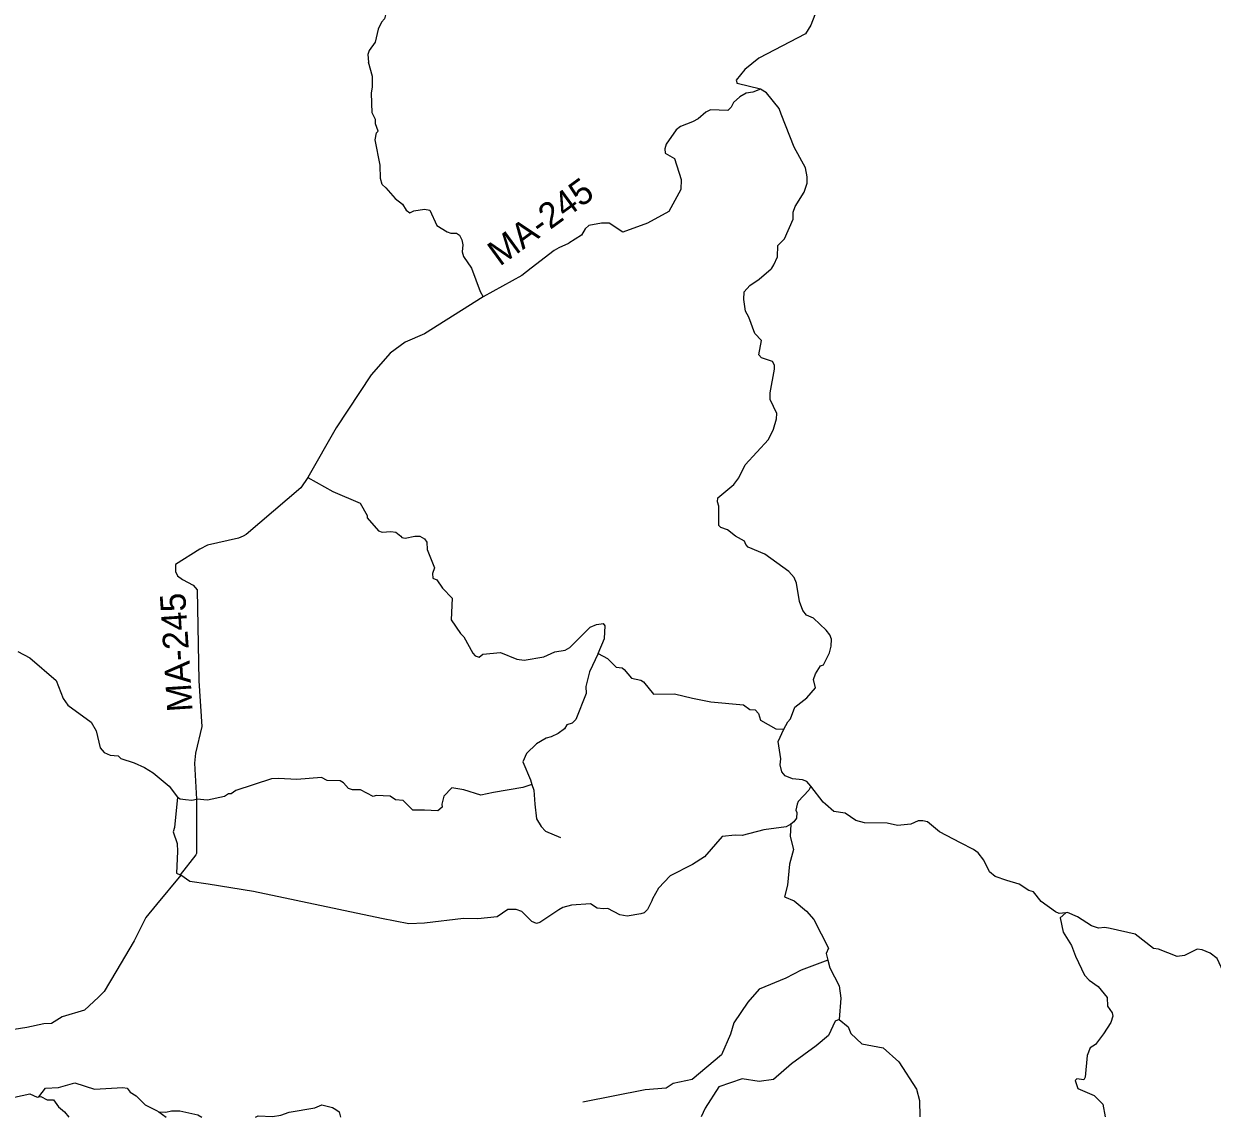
# Model space of a CAD drawing. Extents: x 332 to 501, y 9447 to 9559.
# Drawn here: x 458.02 to 475.76, y 9447.32 to 9463.65 of the extents above; entities that cross this region are included whole.
import ezdxf

# ---------------------------------------------------------------- set-up
doc = ezdxf.new("R2010")
doc.units = 0
for name, color, linetype in [('Level 31', 7, 'Continuous'), ('Level 4', 7, 'Continuous'), ('Level 5', 7, 'Continuous'), ('Level 6', 7, 'Continuous')]:
    doc.layers.add(name, color=color, linetype=linetype)

msp = doc.modelspace()

# ---------------------------------------------------------------- linework, layer by layer
at = {"layer": 'Level 4'}
for points in [[(469.9088, 9464), (469.7674, 9463.6267), (469.6871, 9463.4998), (468.9867, 9463.1333), (468.7796, 9462.9683), (468.6527, 9462.8055), (468.6652, 9462.7597)], [(469.0145, 9462.6735), (468.8979, 9462.6263), (468.7979, 9462.6109), (468.7055, 9462.557), (468.6132, 9462.4724), (468.5748, 9462.404), (468.5251, 9462.3543), (468.269, 9462.362), (468.1964, 9462.3314), (468.0817, 9462.232), (467.9999, 9462.1836)], [(469.0145, 9462.6735), (468.6652, 9462.7597)], [(469.102, 9462.62), (469.0145, 9462.6735)], [(467.9999, 9462.1836), (467.8217, 9462.1173), (467.7567, 9462.0676), (467.6038, 9461.8497), (467.5847, 9461.7809), (467.5923, 9461.7197), (467.73, 9461.6356), (467.8294, 9461.3221), (467.8255, 9461.173), (467.6459, 9460.8442), (467.3267, 9460.6702), (466.9597, 9460.5402), (466.7571, 9460.6702), (466.6386, 9460.674), (466.4513, 9460.6358), (466.3977, 9460.5861), (466.3404, 9460.4943), (466.1531, 9460.3719)], [(466.1504, 9460.3707), (466.003, 9460.3035)], [(466.1531, 9460.3719), (466.1504, 9460.3707)], [(466.003, 9460.3035), (465.9325, 9460.2648), (465.5921, 9460)], [(465.5921, 9460), (465.4508, 9459.8901), (464.876, 9459.574)], [(464.876, 9459.574), (463.9999, 9459.0191)], [(463.9999, 9459.0191), (463.7099, 9458.8942), (463.4881, 9458.7336), (463.2021, 9458.4085), (462.6784, 9457.6153), (462.2574, 9456.8764)], [(462.2574, 9456.8764), (462.1536, 9456.7192), (461.3393, 9456.023), (461.29, 9456)], [(461.29, 9456), (461.2246, 9455.9695), (460.7621, 9455.8624), (460.6435, 9455.805), (460.2804, 9455.5755), (460.2804, 9455.4722), (460.3109, 9455.4072), (460.3874, 9455.3498), (460.548, 9455.2695), (460.6053, 9455.1968), (460.6321, 9453.8418), (460.6779, 9453.1553), (460.5824, 9452.7613), (460.5671, 9452.6083), (460.5935, 9452.0726)], [(460.5935, 9452.0726), (460.5964, 9452)], [(460.5964, 9452), (460.5977, 9451.2609), (460.5838, 9451.2392)], [(460.5838, 9451.2392), (460.3544, 9450.9413)], [(460.3625, 9450.938), (460, 9450.5006)], [(460, 9450.5006), (459.8391, 9450.3064), (459.6658, 9449.9597), (459.392, 9449.493)], [(459.392, 9449.493), (459.22, 9449.1998), (459.1356, 9449.118)], [(459.1356, 9449.118), (458.9228, 9448.921), (458.5884, 9448.8219), (458.4336, 9448.7228), (458.316, 9448.7166), (458.0652, 9448.6651)], [(458.0652, 9448.6651), (457.8764, 9448.636), (457.519, 9448.4954)]]:
    msp.add_lwpolyline(points, dxfattribs=at)
at = {"layer": 'Level 5'}
for points in [[(463.4729, 9464), (463.4013, 9463.7216), (463.3572, 9463.6719), (463.3076, 9463.5695), (463.2635, 9463.3765), (463.1754, 9463.2497), (463.1534, 9463.1891), (463.1644, 9463.0763)], [(463.3076, 9462.0466), (463.2691, 9462.1557), (463.2691, 9462.2218), (463.2195, 9462.321), (463.2085, 9462.6132), (463.225, 9462.707), (463.225, 9462.8613), (463.1644, 9463.0763)], [(469.3222, 9462.2982), (469.29, 9462.382), (469.102, 9462.62)], [(469.5032, 9460.8384), (469.533, 9460.919), (469.665, 9461.133), (469.708, 9461.268), (469.709, 9461.366), (469.684, 9461.5), (469.515, 9461.807), (469.3222, 9462.2982)], [(469.274, 9460.337), (469.373, 9460.436), (469.502, 9460.733)], [(469.502, 9460.733), (469.5032, 9460.8384)], [(469.215, 9460.048), (469.267, 9460.1681), (469.274, 9460.337)], [(468.992, 9459.835), (469.174, 9459.989)], [(469.174, 9459.989), (469.1816, 9460)], [(469.1816, 9460), (469.215, 9460.048)], [(468.7668, 9459.5301), (468.768, 9459.646), (468.855, 9459.743), (468.992, 9459.835)], [(469.1574, 9458.1415), (469.223, 9458.4911), (469.221, 9458.55), (469.1941, 9458.607), (469.028, 9458.662), (468.991, 9458.706), (469.029, 9458.92), (468.927, 9459.024), (468.8379, 9459.27), (468.79, 9459.356), (468.7668, 9459.5301)], [(468.6151, 9456.7693), (468.6879, 9456.869), (468.786, 9457.064), (469.135, 9457.442), (469.209, 9457.598), (469.255, 9457.753), (469.257, 9457.832), (469.156, 9458.0411), (469.1574, 9458.1415)], [(462.2574, 9456.8764), (462.6292, 9456.6679), (463.0362, 9456.4898), (463.1421, 9456.3075), (463.1421, 9456.2736), (463.3117, 9456.0786), (463.3668, 9456.0574), (463.494, 9456.0701), (463.5703, 9456.0574), (463.6467, 9456)], [(468.6424, 9456), (468.522, 9456.093), (468.421, 9456.128), (468.39, 9456.159), (468.39, 9456.445), (468.37, 9456.514), (468.377, 9456.571), (468.6151, 9456.7693)], [(463.9999, 9455.9577), (464.0324, 9455.909), (464.0409, 9455.7988), (464.1469, 9455.5275), (464.1172, 9455.4427), (464.1214, 9455.3706), (464.185, 9455.3452), (464.2656, 9455.2222), (464.414, 9455.0739), (464.397, 9454.7517), (464.5369, 9454.5453), (464.5878, 9454.4986), (464.7192, 9454.2526), (464.7531, 9454.2144), (464.8125, 9454.1932), (464.8718, 9454.2356), (465.1325, 9454.2611), (465.3784, 9454.1635), (465.4886, 9454.1465), (465.7812, 9454.1974), (465.9465, 9454.2738), (466.0991, 9454.295), (466.1669, 9454.3374), (466.4722, 9454.6428), (466.5654, 9454.681), (466.6714, 9454.6937)], [(469.08, 9455.7306), (468.83, 9455.833), (468.793, 9455.874), (468.777, 9455.923), (468.6424, 9456)], [(470.0508, 9454.5239), (469.996, 9454.596), (469.804, 9454.775), (469.702, 9454.82), (469.644, 9454.889), (469.598, 9455.023), (469.552, 9455.296), (469.514, 9455.382), (469.435, 9455.471), (469.08, 9455.7306)], [(469.4212, 9453.2251), (469.462, 9453.27), (469.525, 9453.4451), (469.705, 9453.584), (469.837, 9453.734), (469.804, 9453.861), (469.834, 9453.945), (469.907, 9454.064), (469.953, 9454.08), (470.042, 9454.255), (470.069, 9454.355), (470.074, 9454.459), (470.0508, 9454.5239)], [(457.9286, 9454.2758), (458.1083, 9454.1845), (458.5036, 9453.8441), (458.6063, 9453.5759), (458.6776, 9453.476), (459.0228, 9453.222), (459.0998, 9453.0908), (459.1597, 9452.8396), (459.2196, 9452.7712), (459.3052, 9452.7284), (459.4262, 9452.7202), (459.4685, 9452.6799), (459.6637, 9452.6165), (459.8197, 9452.5461), (459.9476, 9452.4676), (460.099, 9452.3416)], [(466.592, 9454.248), (466.4634, 9453.9713), (466.405, 9453.7557), (466.4095, 9453.6479), (466.2567, 9453.2616), (466.2028, 9453.2077), (466.122, 9453.1807), (466.0905, 9453.1223), (465.9917, 9453.0549), (465.8884, 9453.001), (465.8165, 9452.9831), (465.6683, 9452.8977), (465.52, 9452.754), (465.4661, 9452.6282)], [(466.592, 9454.248), (466.7292, 9454.1719), (466.8597, 9454.0414), (466.9477, 9454.0323), (466.9811, 9454.0081), (467.0903, 9453.8806), (467.2299, 9453.8503), (467.2693, 9453.823), (467.415, 9453.6379), (467.7305, 9453.647), (467.9999, 9453.5821)], [(467.9999, 9453.5821), (468.2726, 9453.5259), (468.7611, 9453.4804), (468.8552, 9453.4136), (468.9341, 9453.4045), (468.9826, 9453.3498), (469.013, 9453.2527), (469.2405, 9453.1221), (469.3635, 9453.1162)], [(469.7653, 9452.2662), (469.706, 9452.334), (469.641, 9452.359), (469.491, 9452.378), (469.383, 9452.421), (469.331, 9452.483), (469.308, 9452.586), (469.317, 9452.675), (469.275, 9452.934), (469.3635, 9453.1162)], [(469.3635, 9453.1162), (469.4212, 9453.2251)], [(460.099, 9452.3416), (460.187, 9452.2665), (460.3098, 9452.1049)], [(469.7653, 9452.2662), (469.7357, 9452.2047), (469.5754, 9452.0364), (469.5609, 9452)], [(469.9489, 9452.028), (469.7653, 9452.2662)], [(460.3098, 9452.1049), (460.2678, 9451.6494)], [(460.3098, 9452.1049), (460.3502, 9452.08), (460.4295, 9452.0691), (460.5274, 9452.0598), (460.5935, 9452.0726)], [(460.5935, 9452.0726), (460.5984, 9452.0735)], [(469.9838, 9452), (469.9489, 9452.028)], [(469.5609, 9452), (469.5394, 9451.9082), (469.5554, 9451.8721), (469.5514, 9451.788), (469.5113, 9451.7319), (469.4646, 9451.6998)], [(471.4366, 9451.75), (471.367, 9451.75), (471.259, 9451.697), (471.061, 9451.678), (470.905, 9451.715), (470.565, 9451.718), (470.435, 9451.756), (470.275, 9451.864), (470.1099, 9451.89), (469.9838, 9452)], [(460.2678, 9451.6494), (460.2463, 9451.5865), (460.3088, 9451.4123), (460.3115, 9451.291)], [(469.4646, 9451.6998), (469.3951, 9451.6597), (469.0626, 9451.6157), (468.738, 9451.5315), (468.6338, 9451.5355)], [(469.4646, 9451.6998), (469.4579, 9451.5175), (469.5064, 9451.3234), (469.4482, 9451.1001), (469.4191, 9450.7894), (469.3706, 9450.6146), (469.5161, 9450.5564), (469.7005, 9450.4011), (469.8073, 9450.2748), (470.0305, 9449.8477), (469.9917, 9449.77), (470.0188, 9449.6705)], [(472, 9451.4195), (471.683, 9451.583), (471.504, 9451.735), (471.4366, 9451.75)], [(468.6338, 9451.5355), (468.44, 9451.517), (468.177, 9451.21), (467.9999, 9451.0969)], [(472.688, 9450.8564), (472.515, 9450.919), (472.431, 9450.989), (472.347, 9451.164), (472.262, 9451.271), (472.191, 9451.323), (472, 9451.4195)], [(460.3115, 9451.2897), (460.2954, 9450.9655), (460.3544, 9450.9413)], [(460.3115, 9451.291), (460.3115, 9451.2897)], [(460.3544, 9450.9413), (460.3625, 9450.938)], [(467.9999, 9451.0969), (467.666, 9450.93), (467.49, 9450.746), (467.4027, 9450.5843)], [(460.772, 9450.806), (460.495, 9450.844), (460.3625, 9450.938)], [(461.4475, 9450.6919), (460.772, 9450.806)], [(473.5685, 9450.3756), (473.469, 9450.3639), (473.416, 9450.389), (473.202, 9450.544), (473.089, 9450.688), (473.017, 9450.711), (472.872, 9450.803), (472.688, 9450.8564)], [(463.3553, 9450.2904), (461.4475, 9450.6919)], [(465.719, 9450.2313), (465.6689, 9450.215), (465.6, 9450.245), (465.451, 9450.395), (465.369, 9450.426), (465.245, 9450.426), (465.084, 9450.314), (464.794, 9450.286), (464.5824, 9450.2906)], [(466.0028, 9450.4204), (465.719, 9450.2313)], [(467.2278, 9450.3614), (467.022, 9450.325), (466.915, 9450.344), (466.734, 9450.442), (466.669, 9450.433), (466.577, 9450.445), (466.474, 9450.511), (466.193, 9450.49), (466.062, 9450.457), (466.0028, 9450.4204)], [(467.3258, 9450.4237), (467.278, 9450.375), (467.2278, 9450.3614)], [(467.3896, 9450.5536), (467.3258, 9450.4237)], [(467.4027, 9450.5843), (467.3896, 9450.5536)], [(463.9999, 9450.2238), (463.766, 9450.213), (463.3553, 9450.2904)], [(464.5824, 9450.2906), (463.9999, 9450.2238)], [(473.5685, 9450.3756), (473.486, 9450.303), (473.531, 9450.086), (473.657, 9449.889), (473.713, 9449.727), (473.852, 9449.443), (473.918, 9449.371)], [(474.0569, 9450.1445), (473.955, 9450.183), (473.745, 9450.315), (473.597, 9450.379), (473.5685, 9450.3756)], [(474.605, 9450.058), (474.232, 9450.143), (474.152, 9450.155), (474.0569, 9450.1445)], [(475.9999, 9449.4078), (475.95, 9449.437), (475.829, 9449.693), (475.723, 9449.776), (475.608, 9449.825), (475.53, 9449.835), (475.344, 9449.741), (475.231, 9449.724), (474.956, 9449.835), (474.88, 9449.842), (474.6066, 9450.0571)], [(470.0188, 9449.6705), (469.6229, 9449.5176), (469.39, 9449.4011), (468.9921, 9449.236), (468.8271, 9449.0419), (468.6136, 9448.7312), (468.5651, 9448.5661), (468.4292, 9448.2555), (467.9925, 9447.8865), (467.7111, 9447.8283), (467.6043, 9447.7603), (467.2938, 9447.7312), (466.3622, 9447.5467)], [(470.0188, 9449.6705), (470.0499, 9449.5564), (470.1857, 9449.2846), (470.2149, 9449.1001), (470.1887, 9448.7816)], [(473.918, 9449.371), (474.0557, 9449.2771), (474.1857, 9449.11), (474.195, 9448.98), (474.2646, 9448.8825), (474.2739, 9448.8314), (474.2414, 9448.7386), (474.1346, 9448.5668), (474.0139, 9448.4089), (473.935, 9448.3579), (473.8886, 9448.2465), (473.8607, 9447.9215), (473.8375, 9447.8843), (473.7354, 9447.8983), (473.7122, 9447.8704), (473.7493, 9447.7543), (473.9954, 9447.6476), (474.1254, 9447.5176), (474.1572, 9447.3311)], [(470.1887, 9448.7816), (470.1275, 9448.7603), (470.0305, 9448.5467), (469.8461, 9448.3914), (469.4773, 9448.1196), (469.2056, 9447.8865), (468.9921, 9447.8574), (468.7398, 9447.8963), (468.3904, 9447.7798), (468.1866, 9447.4594), (468.1266, 9447.3287)], [(470.1887, 9448.7816), (470.3216, 9448.6729), (470.3604, 9448.5759), (470.5254, 9448.4205), (470.8457, 9448.3623), (471.0786, 9448.1487), (471.3406, 9447.7409), (471.3891, 9447.5759), (471.3909, 9447.33)], [(458.2443, 9447.6294), (458.3418, 9447.7595), (458.5352, 9447.7679), (458.7792, 9447.8352), (459.0735, 9447.7426), (459.4941, 9447.7679), (459.5614, 9447.7595), (459.6034, 9447.7006), (459.6959, 9447.6416), (459.8305, 9447.507), (460, 9447.4222)], [(457.6702, 9447.6234), (457.8792, 9447.6248), (458.1063, 9447.6753), (458.2156, 9447.6248), (458.2443, 9447.6294)], [(458.2443, 9447.6294), (458.2745, 9447.6332), (458.367, 9447.5827), (458.4595, 9447.5827), (458.5352, 9447.4817), (458.6278, 9447.406), (458.6911, 9447.324)], [(460.0324, 9447.406), (460.1397, 9447.3985), (460.2212, 9447.4211), (460.3479, 9447.4211), (460.615, 9447.3623), (460.6765, 9447.325)], [(461.4782, 9447.3255), (461.5158, 9447.3442), (461.7285, 9447.3351), (461.8553, 9447.3532), (461.9775, 9447.3985), (462.3623, 9447.4664), (462.4664, 9447.5071), (462.6248, 9447.4709), (462.6746, 9447.4392), (462.7244, 9447.403), (462.7436, 9447.3261)]]:
    msp.add_lwpolyline(points, dxfattribs=at)
at = {"layer": 'Level 6'}
for points in [[(463.4233, 9461.1975), (463.3682, 9461.2472), (463.3407, 9461.3409), (463.3352, 9461.5394), (463.2635, 9461.9142), (463.2801, 9462.019)], [(463.2801, 9462.019), (463.3076, 9462.0466)], [(463.4233, 9461.1975), (463.563, 9461.04), (463.67, 9460.957), (463.725, 9460.867), (463.778, 9460.828), (463.842, 9460.855), (463.9999, 9460.8824)], [(463.9999, 9460.8824), (464.078, 9460.868), (464.184, 9460.638), (464.335, 9460.544), (464.393, 9460.524), (464.477, 9460.521), (464.522, 9460.493), (464.558, 9460.421), (464.572, 9460.348), (464.563, 9460.246), (464.582, 9460.175), (464.7004, 9460)], [(464.7004, 9460), (464.828, 9459.653), (464.876, 9459.574)], [(463.6467, 9456), (463.6593, 9455.9811), (463.7102, 9455.9684), (463.8524, 9456)], [(463.8524, 9456), (463.8991, 9456)], [(463.8991, 9456), (463.9307, 9455.998), (463.9999, 9455.9577)], [(466.694, 9454.661), (466.6714, 9454.6937)], [(466.592, 9454.248), (466.683, 9454.469), (466.694, 9454.661)], [(465.4661, 9452.6282), (465.5829, 9452.3612), (465.6007, 9452.2892)], [(463.7364, 9452), (463.6811, 9452.0511), (463.5643, 9452.0646), (463.488, 9452.1185), (463.2768, 9452.1275), (463.2319, 9452.114), (463.0432, 9452.2129), (462.9264, 9452.2129), (462.8635, 9452.2309), (462.7917, 9452.3163), (462.7378, 9452.3477), (462.5465, 9452.3522), (462.4612, 9452.3972), (462.0928, 9452.3657), (461.8188, 9452.3837), (461.7155, 9452.3747), (461.1823, 9452.2039), (461.1149, 9452.1545), (461.0745, 9452.15), (461.0116, 9452.114), (460.7601, 9452.0556), (460.5984, 9452.0735)], [(465.0308, 9452.1731), (464.8401, 9452.132), (464.584, 9452.2129), (464.4088, 9452.2399), (464.2875, 9452.1185), (464.2579, 9452)], [(465.6007, 9452.2892), (465.4661, 9452.2488), (465.0308, 9452.1731)], [(465.6007, 9452.2892), (465.6323, 9452.2084), (465.6453, 9452)], [(463.9999, 9451.9094), (463.8249, 9451.9072), (463.7364, 9452)], [(464.2579, 9452), (464.2606, 9451.9522), (464.1977, 9451.8983), (463.9999, 9451.9094)], [(465.6453, 9452), (465.6728, 9451.7769), (465.7401, 9451.6645), (465.803, 9451.5926), (466.0276, 9451.5027)], [(474.6066, 9450.0571), (474.605, 9450.058)], [(460, 9447.4222), (460.0324, 9447.406)], [(460.0324, 9447.406), (460.1444, 9447.3248)]]:
    msp.add_lwpolyline(points, dxfattribs=at)

# ---------------------------------------------------------------- texts
at = {"layer": 'Level 31'}
for rotation, p in [(36.12384, (465.1223, 9460.0196)), (93.64442, (460.5392, 9453.3867))]:
    msp.add_text('MA-245', height=0.38, rotation=rotation, dxfattribs=at).set_placement(p)

doc.saveas('drawing.dxf')
